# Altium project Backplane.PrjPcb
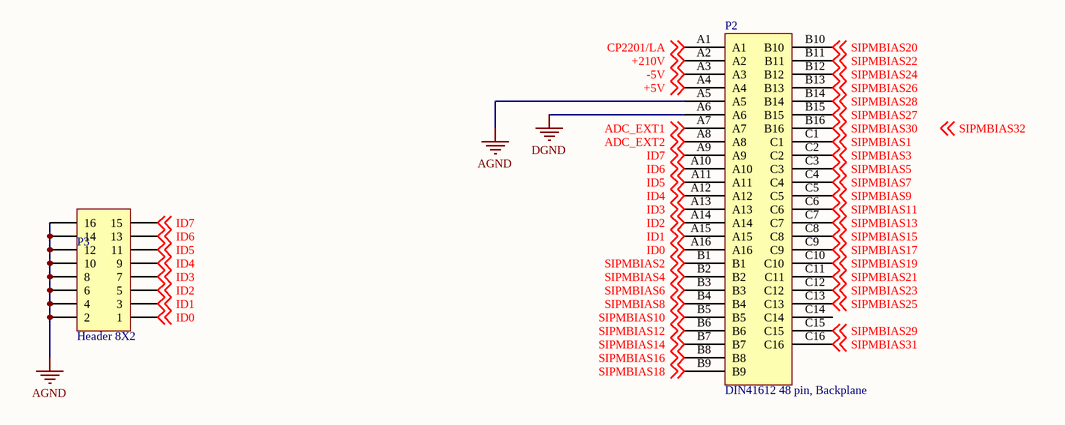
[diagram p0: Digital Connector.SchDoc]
3 sheets, 21 parts. Net scope: global (net labels, ports and power ports of the same name join across sheets).
Board files: Backplane_New.PcbDoc, Backplane_Tight.PcbDoc
Sheets:
  Digital Connector.SchDoc
  Analog Connector.SchDoc
  LEMO.SchDoc

## Sheet Digital Connector.SchDoc
size A

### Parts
P2  DIN41612 48 pin, Backplane  [EURO2.54-2V48]
P3  Header 8X2  [HDR2X8]

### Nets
AGND: P2.A5 P3.2 P3.4 P3.6 P3.8 P3.10 P3.12 P3.14 P3.16
DGND: P2.A6
+5V: P2.A4 ; off-sheet +5V
+210V: P2.A2 ; off-sheet +210V
-5V: P2.A3 ; off-sheet -5V
ADC_EXT1: P2.A7 ; off-sheet ADC_EXT1
ADC_EXT2: P2.A8 ; off-sheet ADC_EXT2
CP2201/LA: P2.A1 ; off-sheet CP2201/LA
ID0: P2.A16 P3.1 ; off-sheet ID0
ID1: P2.A15 P3.3 ; off-sheet ID1
ID2: P2.A14 P3.5 ; off-sheet ID2
ID3: P2.A13 P3.7 ; off-sheet ID3
ID4: P2.A12 P3.9 ; off-sheet ID4
ID5: P2.A11 P3.11 ; off-sheet ID5
ID6: P2.A10 P3.13 ; off-sheet ID6
ID7: P2.A9 P3.15 ; off-sheet ID7
SIPMBIAS1: P2.C1 ; off-sheet SIPMBIAS1
SIPMBIAS2: P2.B1 ; off-sheet SIPMBIAS2
SIPMBIAS3: P2.C2 ; off-sheet SIPMBIAS3
SIPMBIAS4: P2.B2 ; off-sheet SIPMBIAS4
SIPMBIAS5: P2.C3 ; off-sheet SIPMBIAS5
SIPMBIAS6: P2.B3 ; off-sheet SIPMBIAS6
SIPMBIAS7: P2.C4 ; off-sheet SIPMBIAS7
SIPMBIAS8: P2.B4 ; off-sheet SIPMBIAS8
SIPMBIAS9: P2.C5 ; off-sheet SIPMBIAS9
SIPMBIAS10: P2.B5 ; off-sheet SIPMBIAS10
SIPMBIAS11: P2.C6 ; off-sheet SIPMBIAS11
SIPMBIAS12: P2.B6 ; off-sheet SIPMBIAS12
SIPMBIAS13: P2.C7 ; off-sheet SIPMBIAS13
SIPMBIAS14: P2.B7 ; off-sheet SIPMBIAS14
SIPMBIAS15: P2.C8 ; off-sheet SIPMBIAS15
SIPMBIAS16: P2.B8 ; off-sheet SIPMBIAS16
SIPMBIAS17: P2.C9 ; off-sheet SIPMBIAS17
SIPMBIAS18: P2.B9 ; off-sheet SIPMBIAS18
SIPMBIAS19: P2.C10 ; off-sheet SIPMBIAS19
SIPMBIAS20: P2.B10 ; off-sheet SIPMBIAS20
SIPMBIAS21: P2.C11 ; off-sheet SIPMBIAS21
SIPMBIAS22: P2.B11 ; off-sheet SIPMBIAS22
SIPMBIAS23: P2.C12 ; off-sheet SIPMBIAS23
SIPMBIAS24: P2.B12 ; off-sheet SIPMBIAS24
SIPMBIAS25: P2.C13 ; off-sheet SIPMBIAS25
SIPMBIAS26: P2.B13 ; off-sheet SIPMBIAS26
SIPMBIAS27: P2.B15 ; off-sheet SIPMBIAS27
SIPMBIAS28: P2.B14 ; off-sheet SIPMBIAS28
SIPMBIAS29: P2.C15 ; off-sheet SIPMBIAS29
SIPMBIAS30: P2.B16 ; off-sheet SIPMBIAS30
SIPMBIAS31: P2.C16 ; off-sheet SIPMBIAS31

Not connected (* = marked no-connect by the designer): P2 C14

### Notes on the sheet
- Labels drawn without touching a wire or pin: SIPMBIAS32

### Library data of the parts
P3 = Header 8X2: Header, 8-Pin, Dual row

## Sheet Analog Connector.SchDoc
size A
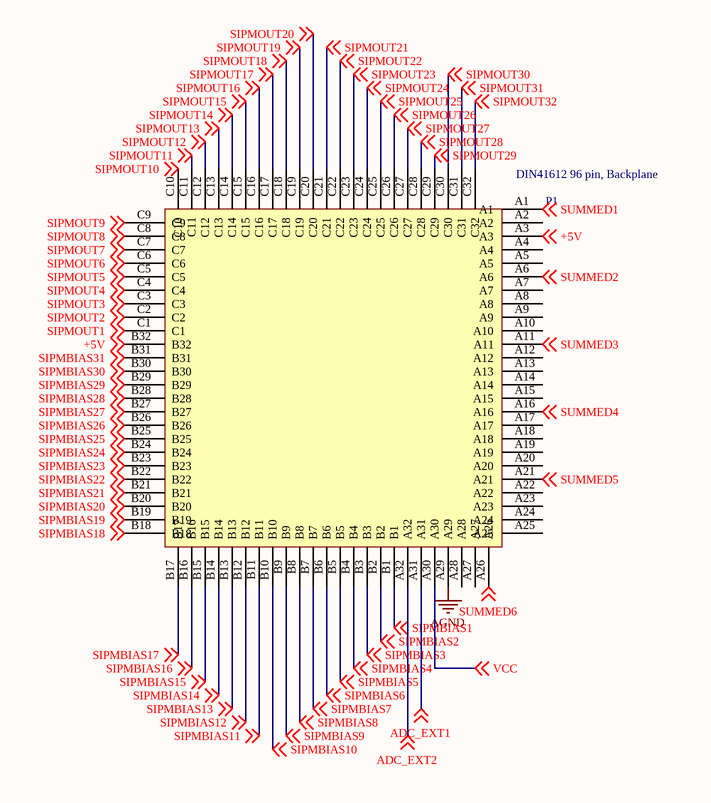
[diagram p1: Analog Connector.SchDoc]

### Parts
P1  DIN41612 96 pin, Backplane  [EURO2.54-2V96]

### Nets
AGND: P1.A29
+5V: P1.A3 P1.B32 ; off-sheet +5V
ADC_EXT1: P1.A31 ; off-sheet ADC_EXT1
ADC_EXT2: P1.A32 ; off-sheet ADC_EXT2
SIPMBIAS1: P1.B1 ; off-sheet SIPMBIAS1
SIPMBIAS2: P1.B2 ; off-sheet SIPMBIAS2
SIPMBIAS3: P1.B3 ; off-sheet SIPMBIAS3
SIPMBIAS4: P1.B4 ; off-sheet SIPMBIAS4
SIPMBIAS5: P1.B5 ; off-sheet SIPMBIAS5
SIPMBIAS6: P1.B6 ; off-sheet SIPMBIAS6
SIPMBIAS7: P1.B7 ; off-sheet SIPMBIAS7
SIPMBIAS8: P1.B8 ; off-sheet SIPMBIAS8
SIPMBIAS9: P1.B9 ; off-sheet SIPMBIAS9
SIPMBIAS10: P1.B10 ; off-sheet SIPMBIAS10
SIPMBIAS11: P1.B11 ; off-sheet SIPMBIAS11
SIPMBIAS12: P1.B12 ; off-sheet SIPMBIAS12
SIPMBIAS13: P1.B13 ; off-sheet SIPMBIAS13
SIPMBIAS14: P1.B14 ; off-sheet SIPMBIAS14
SIPMBIAS15: P1.B15 ; off-sheet SIPMBIAS15
SIPMBIAS16: P1.B16 ; off-sheet SIPMBIAS16
SIPMBIAS17: P1.B17 ; off-sheet SIPMBIAS17
SIPMBIAS18: P1.B18 ; off-sheet SIPMBIAS18
SIPMBIAS19: P1.B19 ; off-sheet SIPMBIAS19
SIPMBIAS20: P1.B20 ; off-sheet SIPMBIAS20
SIPMBIAS21: P1.B21 ; off-sheet SIPMBIAS21
SIPMBIAS22: P1.B22 ; off-sheet SIPMBIAS22
SIPMBIAS23: P1.B23 ; off-sheet SIPMBIAS23
SIPMBIAS24: P1.B24 ; off-sheet SIPMBIAS24
SIPMBIAS25: P1.B25 ; off-sheet SIPMBIAS25
SIPMBIAS26: P1.B26 ; off-sheet SIPMBIAS26
SIPMBIAS27: P1.B27 ; off-sheet SIPMBIAS27
SIPMBIAS28: P1.B28 ; off-sheet SIPMBIAS28
SIPMBIAS29: P1.B29 ; off-sheet SIPMBIAS29
SIPMBIAS30: P1.B30 ; off-sheet SIPMBIAS30
SIPMBIAS31: P1.B31 ; off-sheet SIPMBIAS31
SIPMOUT1: P1.C1 ; off-sheet SIPMOUT1
SIPMOUT2: P1.C2 ; off-sheet SIPMOUT2
SIPMOUT3: P1.C3 ; off-sheet SIPMOUT3
SIPMOUT4: P1.C4 ; off-sheet SIPMOUT4
SIPMOUT5: P1.C5 ; off-sheet SIPMOUT5
SIPMOUT6: P1.C6 ; off-sheet SIPMOUT6
SIPMOUT7: P1.C7 ; off-sheet SIPMOUT7
SIPMOUT8: P1.C8 ; off-sheet SIPMOUT8
SIPMOUT9: P1.C9 ; off-sheet SIPMOUT9
SIPMOUT10: P1.C10 ; off-sheet SIPMOUT10
SIPMOUT11: P1.C11 ; off-sheet SIPMOUT11
SIPMOUT12: P1.C12 ; off-sheet SIPMOUT12
SIPMOUT13: P1.C13 ; off-sheet SIPMOUT13
SIPMOUT14: P1.C14 ; off-sheet SIPMOUT14
SIPMOUT15: P1.C15 ; off-sheet SIPMOUT15
SIPMOUT16: P1.C16 ; off-sheet SIPMOUT16
SIPMOUT17: P1.C17 ; off-sheet SIPMOUT17
SIPMOUT18: P1.C18 ; off-sheet SIPMOUT18
SIPMOUT19: P1.C19 ; off-sheet SIPMOUT19
SIPMOUT20: P1.C20 ; off-sheet SIPMOUT20
SIPMOUT21: P1.C21 ; off-sheet SIPMOUT21
SIPMOUT22: P1.C22 ; off-sheet SIPMOUT22
SIPMOUT23: P1.C23 ; off-sheet SIPMOUT23
SIPMOUT24: P1.C24 ; off-sheet SIPMOUT24
SIPMOUT25: P1.C25 ; off-sheet SIPMOUT25
SIPMOUT26: P1.C26 ; off-sheet SIPMOUT26
SIPMOUT27: P1.C27 ; off-sheet SIPMOUT27
SIPMOUT28: P1.C28 ; off-sheet SIPMOUT28
SIPMOUT29: P1.C29 ; off-sheet SIPMOUT29
SIPMOUT30: P1.C30 ; off-sheet SIPMOUT30
SIPMOUT31: P1.C31 ; off-sheet SIPMOUT31
SIPMOUT32: P1.C32 ; off-sheet SIPMOUT32
SUMMED1: P1.A1 ; off-sheet SUMMED1
SUMMED2: P1.A6 ; off-sheet SUMMED2
SUMMED3: P1.A11 ; off-sheet SUMMED3
SUMMED4: P1.A16 ; off-sheet SUMMED4
SUMMED5: P1.A21 ; off-sheet SUMMED5
SUMMED6: P1.A26 ; off-sheet SUMMED6
VCC: P1.A30 ; off-sheet VCC

Not connected (* = marked no-connect by the designer): P1 A2 A4 A5 A7 A8 A9 A10 A12 A13 A14 A15 A17 A18 A19 A20 A22 A23 A24 A25 A27 A28

## Sheet LEMO.SchDoc
size A
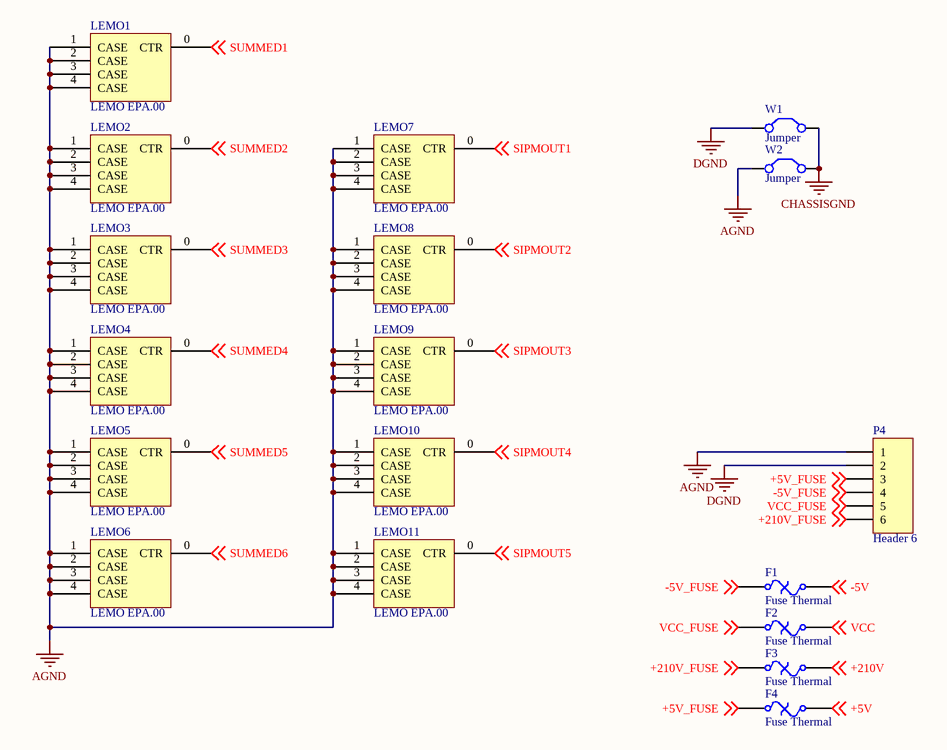
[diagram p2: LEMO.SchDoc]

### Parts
F1  Fuse Thermal  [CAPC4532M]
F2  Fuse Thermal  [RAD-0.2]
F3  Fuse Thermal  [RAD-0.2]
F4  Fuse Thermal  [RAD-0.2]
LEMO1  LEMO EPA.00  [LEMO EPA.00]
LEMO2  LEMO EPA.00  [LEMO EPA.00]
LEMO3  LEMO EPA.00  [LEMO EPA.00]
LEMO4  LEMO EPA.00  [LEMO EPA.00]
LEMO5  LEMO EPA.00  [LEMO EPA.00]
LEMO6  LEMO EPA.00  [LEMO EPA.00]
LEMO7  LEMO EPA.00  [LEMO EPA.00]
LEMO8  LEMO EPA.00  [LEMO EPA.00]
LEMO9  LEMO EPA.00  [LEMO EPA.00]
LEMO10  LEMO EPA.00  [LEMO EPA.00]
LEMO11  LEMO EPA.00  [LEMO EPA.00]
P4  Header 6  [KK6373]
W1  Jumper  [HDR1X2]
W2  Jumper  [HDR1X2]

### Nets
AGND: LEMO1.1(CASE) LEMO1.2(CASE) LEMO1.3(CASE) LEMO1.4(CASE) LEMO2.1(CASE) LEMO2.2(CASE) LEMO2.3(CASE) LEMO2.4(CASE) LEMO3.1(CASE) LEMO3.2(CASE) LEMO3.3(CASE) LEMO3.4(CASE) LEMO4.1(CASE) LEMO4.2(CASE) LEMO4.3(CASE) LEMO4.4(CASE) LEMO5.1(CASE) LEMO5.2(CASE) LEMO5.3(CASE) LEMO5.4(CASE) LEMO6.1(CASE) LEMO6.2(CASE) LEMO6.3(CASE) LEMO6.4(CASE) LEMO7.1(CASE) LEMO7.2(CASE) LEMO7.3(CASE) LEMO7.4(CASE) LEMO8.1(CASE) LEMO8.2(CASE) LEMO8.3(CASE) LEMO8.4(CASE) LEMO9.1(CASE) LEMO9.2(CASE) LEMO9.3(CASE) LEMO9.4(CASE) LEMO10.1(CASE) LEMO10.2(CASE) LEMO10.3(CASE) LEMO10.4(CASE) LEMO11.1(CASE) LEMO11.2(CASE) LEMO11.3(CASE) LEMO11.4(CASE) P4.1 W2.1(C1)
CHASSISGND: W1.2(C2) W2.2(C2)
DGND: P4.2 W1.1(C1)
+5V: F4.2 ; off-sheet +5V
+5V_FUSE: F4.1 P4.3 ; off-sheet +5V_FUSE
+210V: F3.2 ; off-sheet +210V
+210V_FUSE: F3.1 P4.6 ; off-sheet +210V_FUSE
-5V: F1.2 ; off-sheet -5V
-5V_FUSE: F1.1 P4.4 ; off-sheet -5V_FUSE
SIPMOUT1: LEMO7.0(CTR) ; off-sheet SIPMOUT1
SIPMOUT2: LEMO8.0(CTR) ; off-sheet SIPMOUT2
SIPMOUT3: LEMO9.0(CTR) ; off-sheet SIPMOUT3
SIPMOUT4: LEMO10.0(CTR) ; off-sheet SIPMOUT4
SIPMOUT5: LEMO11.0(CTR) ; off-sheet SIPMOUT5
SUMMED1: LEMO1.0(CTR) ; off-sheet SUMMED1
SUMMED2: LEMO2.0(CTR) ; off-sheet SUMMED2
SUMMED3: LEMO3.0(CTR) ; off-sheet SUMMED3
SUMMED4: LEMO4.0(CTR) ; off-sheet SUMMED4
SUMMED5: LEMO5.0(CTR) ; off-sheet SUMMED5
SUMMED6: LEMO6.0(CTR) ; off-sheet SUMMED6
VCC: F2.2 ; off-sheet VCC
VCC_FUSE: F2.1 P4.5 ; off-sheet VCC_FUSE

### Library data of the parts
F1-F4 = Fuse Thermal: Thermal Fuse
P4 = Header 6: Header, 6-Pin
W1 W2 = Jumper: Jumper Wire

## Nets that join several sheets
AGND: Digital Connector (9 pins), Analog Connector (P1.A29), LEMO (46 pins)
DGND: Digital Connector (P2.A6), LEMO (P4.2 W1.1)
+5V: Digital Connector (P2.A4), Analog Connector (P1.A3 P1.B32), LEMO (F4.2)
+210V: Digital Connector (P2.A2), LEMO (F3.2)
-5V: Digital Connector (P2.A3), LEMO (F1.2)
ADC_EXT1: Digital Connector (P2.A7), Analog Connector (P1.A31)
ADC_EXT2: Digital Connector (P2.A8), Analog Connector (P1.A32)
SIPMBIAS1: Digital Connector (P2.C1), Analog Connector (P1.B1)
SIPMBIAS2: Digital Connector (P2.B1), Analog Connector (P1.B2)
SIPMBIAS3: Digital Connector (P2.C2), Analog Connector (P1.B3)
SIPMBIAS4: Digital Connector (P2.B2), Analog Connector (P1.B4)
SIPMBIAS5: Digital Connector (P2.C3), Analog Connector (P1.B5)
SIPMBIAS6: Digital Connector (P2.B3), Analog Connector (P1.B6)
SIPMBIAS7: Digital Connector (P2.C4), Analog Connector (P1.B7)
SIPMBIAS8: Digital Connector (P2.B4), Analog Connector (P1.B8)
SIPMBIAS9: Digital Connector (P2.C5), Analog Connector (P1.B9)
SIPMBIAS10: Digital Connector (P2.B5), Analog Connector (P1.B10)
SIPMBIAS11: Digital Connector (P2.C6), Analog Connector (P1.B11)
SIPMBIAS12: Digital Connector (P2.B6), Analog Connector (P1.B12)
SIPMBIAS13: Digital Connector (P2.C7), Analog Connector (P1.B13)
SIPMBIAS14: Digital Connector (P2.B7), Analog Connector (P1.B14)
SIPMBIAS15: Digital Connector (P2.C8), Analog Connector (P1.B15)
SIPMBIAS16: Digital Connector (P2.B8), Analog Connector (P1.B16)
SIPMBIAS17: Digital Connector (P2.C9), Analog Connector (P1.B17)
SIPMBIAS18: Digital Connector (P2.B9), Analog Connector (P1.B18)
SIPMBIAS19: Digital Connector (P2.C10), Analog Connector (P1.B19)
SIPMBIAS20: Digital Connector (P2.B10), Analog Connector (P1.B20)
SIPMBIAS21: Digital Connector (P2.C11), Analog Connector (P1.B21)
SIPMBIAS22: Digital Connector (P2.B11), Analog Connector (P1.B22)
SIPMBIAS23: Digital Connector (P2.C12), Analog Connector (P1.B23)
SIPMBIAS24: Digital Connector (P2.B12), Analog Connector (P1.B24)
SIPMBIAS25: Digital Connector (P2.C13), Analog Connector (P1.B25)
SIPMBIAS26: Digital Connector (P2.B13), Analog Connector (P1.B26)
SIPMBIAS27: Digital Connector (P2.B15), Analog Connector (P1.B27)
SIPMBIAS28: Digital Connector (P2.B14), Analog Connector (P1.B28)
SIPMBIAS29: Digital Connector (P2.C15), Analog Connector (P1.B29)
SIPMBIAS30: Digital Connector (P2.B16), Analog Connector (P1.B30)
SIPMBIAS31: Digital Connector (P2.C16), Analog Connector (P1.B31)
SIPMOUT1: Analog Connector (P1.C1), LEMO (LEMO7.0)
SIPMOUT2: Analog Connector (P1.C2), LEMO (LEMO8.0)
SIPMOUT3: Analog Connector (P1.C3), LEMO (LEMO9.0)
SIPMOUT4: Analog Connector (P1.C4), LEMO (LEMO10.0)
SIPMOUT5: Analog Connector (P1.C5), LEMO (LEMO11.0)
SUMMED1: Analog Connector (P1.A1), LEMO (LEMO1.0)
SUMMED2: Analog Connector (P1.A6), LEMO (LEMO2.0)
SUMMED3: Analog Connector (P1.A11), LEMO (LEMO3.0)
SUMMED4: Analog Connector (P1.A16), LEMO (LEMO4.0)
SUMMED5: Analog Connector (P1.A21), LEMO (LEMO5.0)
SUMMED6: Analog Connector (P1.A26), LEMO (LEMO6.0)
VCC: Analog Connector (P1.A30), LEMO (F2.2)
